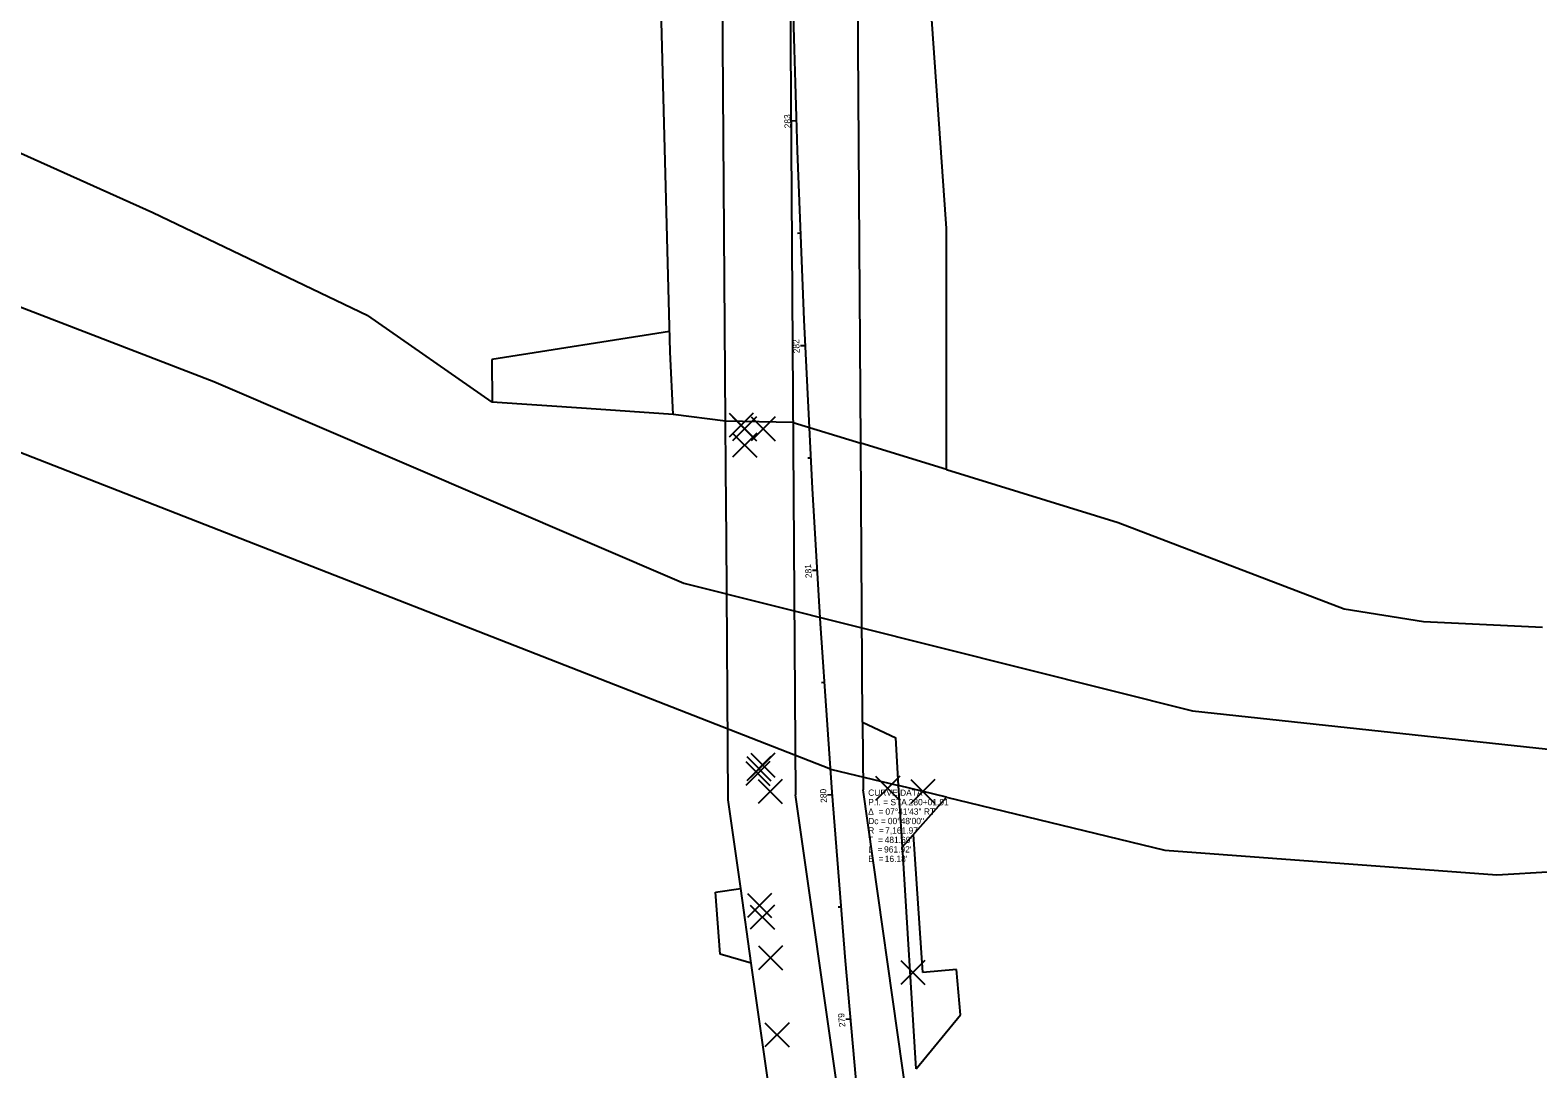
# Model space of a CAD drawing. Extents: x 1721910 to 1725197, y 328771 to 332519.
# Drawn here: x 1722580 to 1723250, y 330805 to 331267 of the extents above; entities that cross this region are included whole.
import ezdxf

# ---------------------------------------------------------------- set-up
doc = ezdxf.new("R2010")
doc.units = 0
for name, color, linetype in [('BR_P_Gen_Approach_Slab', 7, 'Continuous'), ('BR_P_Slab_Object', 7, 'Continuous'), ('DR_P_Ditch', 7, 'Continuous'), ('DR_P_Flood_Boundary', 7, 'Continuous'), ('DT_P_Graded_Shoulder', 7, 'Continuous'), ('MT_P_Work_Area', 7, 'Continuous'), ('PM_X_Lane_Line', 7, 'Continuous'), ('PV_P_Drive', 7, 'Continuous'), ('PV_P_EOP', 7, 'Continuous'), ('RD_P_GR_Rt', 7, 'Continuous'), ('SC_Scratch1', 7, 'Continuous')]:
    doc.layers.add(name, color=color, linetype=linetype)

msp = doc.modelspace()

# ---------------------------------------------------------------- linework, layer by layer
at = {"layer": 'BR_P_Gen_Approach_Slab'}
for p, q in [((1722889.04, 331093.19), (1722884.82, 331710.44)), ((1722949.11, 331083.44), (1722944.82, 331710.85)), ((1722916.88, 331408.8), (1722920.17, 330927.13)), ((1722949.95, 330959.48), (1722950.16, 330929.35)), ((1722978.45, 330730.26), (1722950.16, 330929.35)), ((1722987.94, 330450.23), (1722920.17, 330927.13))]:
    msp.add_line(p, q, dxfattribs=at)
at = {"layer": 'BR_P_Slab_Object'}
msp.add_lwpolyline([(1722131.62, 331191.29), (1722412.26, 331207.03), (1722661.62, 331110.8), (1722870.54, 331021.28), (1723096.57, 330964.56), (1723308.08, 330941.73), (1723482.96, 330982.54)], dxfattribs=at)
at = {"layer": 'DR_P_Flood_Boundary'}
for p, q in [((1722864.19, 331133.05), (1722785.15, 331120.7)), ((1722785.15, 331120.7), (1722785.4, 331101.7)), ((1722827.29, 331098.84), (1722785.4, 331101.7)), ((1722865.77, 331096.21), (1722827.29, 331098.84))]:
    msp.add_line(p, q, dxfattribs=at)
at = {"layer": 'DT_P_Graded_Shoulder'}
msp.add_arc((1730078.68, 331457.77), 7161.97, 180.391728, 188.087121, dxfattribs=at)
at = {"layer": 'MT_P_Work_Area'}
for p, q in [((1722890.66, 331096.78), (1722901.35, 331086.08)), ((1722901.35, 331096.78), (1722890.66, 331086.08)), ((1722892.17, 331095.14), (1722902.86, 331084.45)), ((1722902.86, 331095.14), (1722892.17, 331084.45)), ((1722896, 331091.43), (1722896, 331091.43)), ((1722897.51, 331089.8), (1722897.51, 331089.8)), ((1722900.38, 331095.15), (1722911.07, 331084.46)), ((1722911.07, 331095.15), (1722900.38, 331084.46)), ((1722905.72, 331089.81), (1722905.72, 331089.81)), ((1722892.19, 331087.95), (1722902.88, 331077.26)), ((1722902.88, 331087.95), (1722892.19, 331077.26)), ((1722897.53, 331082.6), (1722897.53, 331082.6)), ((1722898.01, 330942.01), (1722908.7, 330931.32)), ((1722908.7, 330942.01), (1722898.01, 330931.32)), ((1722898.48, 330944.13), (1722909.17, 330933.44)), ((1722909.17, 330944.13), (1722898.48, 330933.44)), ((1722900.3, 330945.63), (1722910.99, 330934.94)), ((1722910.99, 330945.63), (1722900.3, 330934.94)), ((1722903.36, 330936.67), (1722903.36, 330936.67)), ((1722903.82, 330938.79), (1722903.82, 330938.79)), ((1722905.64, 330940.28), (1722905.64, 330940.28)), ((1722955.72, 330935.39), (1722966.41, 330924.69)), ((1722966.41, 330935.39), (1722955.72, 330924.69)), ((1722903.54, 330933.95), (1722914.23, 330923.26)), ((1722914.23, 330933.95), (1722903.54, 330923.26)), ((1722908.88, 330928.61), (1722908.88, 330928.61)), ((1722961.06, 330930.04), (1722961.06, 330930.04)), ((1722971.37, 330934.04), (1722982.06, 330923.35)), ((1722982.06, 330934.04), (1722971.37, 330923.35)), ((1722976.72, 330928.69), (1722976.72, 330928.69)), ((1722898.82, 330883.31), (1722909.51, 330872.62)), ((1722909.51, 330883.31), (1722898.82, 330872.62)), ((1722900.03, 330878.16), (1722910.73, 330867.47)), ((1722910.73, 330878.16), (1722900.03, 330867.47)), ((1722904.17, 330877.96), (1722904.17, 330877.96)), ((1722905.38, 330872.82), (1722905.38, 330872.82)), ((1722903.61, 330860.05), (1722914.3, 330849.36)), ((1722914.3, 330860.05), (1722903.61, 330849.36)), ((1722908.96, 330854.71), (1722908.96, 330854.71)), ((1722966.95, 330853.59), (1722977.64, 330842.9)), ((1722977.64, 330853.59), (1722966.95, 330842.9)), ((1722972.29, 330848.24), (1722972.29, 330848.24)), ((1722906.54, 330825.79), (1722917.23, 330815.1)), ((1722917.23, 330825.79), (1722906.54, 330815.1)), ((1722911.89, 330820.45), (1722911.89, 330820.45))]:
    msp.add_line(p, q, dxfattribs=at)
at = {"layer": 'PM_X_Lane_Line'}
for p, q in [((1722785.4, 331101.7), (1722730.04, 331140.19)), ((1722935.69, 330938.62), (1722430.49, 331135.91)), ((1722827.29, 331098.84), (1722785.4, 331101.7)), ((1722865.77, 331096.21), (1722827.29, 331098.84)), ((1722889.04, 331093.19), (1722865.77, 331096.21)), ((1722919.04, 331092.69), (1722889.04, 331093.19)), ((1722919.04, 331092.69), (1722949.11, 331083.44)), ((1722987.21, 331071.69), (1722949.11, 331083.44)), ((1722987.21, 331071.71), (1723063.42, 331048.26)), ((1723063.42, 331048.26), (1723163.91, 331009.86)), ((1723163.91, 331009.86), (1723199.1, 331004.21)), ((1723199.1, 331004.21), (1723251.95, 331001.61)), ((1722935.69, 330938.62), (1722965.95, 330931.27)), ((1722987.24, 330926.09), (1722965.95, 330931.27)), ((1722987.24, 330926.09), (1723084.16, 330902.53)), ((1723084.16, 330902.53), (1723231.76, 330891.66)), ((1723231.76, 330891.66), (1723256.72, 330893.13))]:
    msp.add_line(p, q, dxfattribs=at)
msp.add_lwpolyline([(1722434.29, 331257.93), (1722539.23, 331228.82), (1722634.57, 331186.03), (1722730.04, 331140.19)], dxfattribs=at)
at = {"layer": 'PV_P_Drive'}
for p, q in [((1722976.7, 330848.17), (1722972.57, 330909.58)), ((1722884.54, 330883.91), (1722895.79, 330885.51)), ((1722886.71, 330856.33), (1722884.54, 330883.91)), ((1722900.49, 330852.39), (1722886.71, 330856.33)), ((1722991.69, 330849.48), (1722976.7, 330848.17)), ((1722993.45, 330829.33), (1722991.69, 330849.48)), ((1722973.78, 330805.37), (1722993.45, 330829.33))]:
    msp.add_line(p, q, dxfattribs=at)
at = {"layer": 'PV_P_EOP'}
for p, q in [((1722864.43, 331124), (1722856.88, 331408.39)), ((1722987.21, 331071.69), (1722987.2, 331178.83)), ((1722865.77, 331096.21), (1722864.43, 331124)), ((1722889.04, 331093.19), (1722865.77, 331096.21)), ((1722889.18, 331071.89), (1722889.04, 331093.19)), ((1722949.95, 330959.48), (1722949.11, 331083.44)), ((1722987.21, 331071.69), (1722949.11, 331083.44)), ((1722889.4, 331040.83), (1722889.18, 331071.89)), ((1722890.19, 330924.9), (1722889.4, 331040.83)), ((1722949.95, 330959.48), (1722964.63, 330952.5)), ((1722965.95, 330931.27), (1722964.63, 330952.5)), ((1722967.65, 330904.04), (1722965.95, 330931.27)), ((1722895.79, 330885.51), (1722890.19, 330924.9)), ((1722973.78, 330805.37), (1722967.65, 330904.04)), ((1722900.49, 330852.39), (1722895.79, 330885.51)), ((1722916.51, 330739.69), (1722900.49, 330852.39))]:
    msp.add_line(p, q, dxfattribs=at)
msp.add_lwpolyline([(1722987.2, 331178.83), (1722949.82, 331710.89), (1722944.82, 331710.85), (1722944.78, 331715.74)], dxfattribs=at)
at = {"layer": 'RD_P_GR_Rt'}
msp.add_line((1722967.65, 330904.04), (1722987.24, 330926.09), dxfattribs=at)
at = {"layer": 'SC_Scratch1'}
for p, q in [((1722920.44, 331226.69), (1722918.44, 331226.63)), ((1722922.23, 331176.73), (1722921.03, 331176.68)), ((1722924.37, 331126.77), (1722922.37, 331126.68)), ((1722926.85, 331076.83), (1722925.65, 331076.77)), ((1722929.69, 331026.91), (1722927.69, 331026.79)), ((1722932.87, 330977.02), (1722931.67, 330976.94)), ((1722936.4, 330927.14), (1722934.4, 330926.99)), ((1722940.28, 330877.29), (1722939.08, 330877.19)), ((1722944.5, 330827.47), (1722942.51, 330827.29))]:
    msp.add_line(p, q, dxfattribs=at)

# ---------------------------------------------------------------- texts
at = {"layer": 'DR_P_Ditch'}
for s, p in [('CURVE DATA', (1722952.41, 330926.72)), ('P.I. = STA. ', (1722952.41, 330922.52)), ('280+01.91', (1722970.4, 330922.52)), ('Δ  = ', (1722952.41, 330918.32)), ('Dc = ', (1722952.41, 330914.12)), ('07°41\'43" RT', (1722960.06, 330918.32)), ('00°48\'00"', (1722961.15, 330914.12)), ('T  = ', (1722952.41, 330905.72)), ('R  = ', (1722952.41, 330909.92)), ("481.69'", (1722959.73, 330905.72)), ("7,161.97'", (1722959.94, 330909.92)), ('L  = ', (1722952.41, 330901.52)), ("961.92'", (1722959.45, 330901.52)), ('E  = ', (1722952.41, 330897.32)), ("16.18'", (1722959.75, 330897.32))]:
    msp.add_text(s, height=2.8, dxfattribs=at).set_placement(p)
at = {"layer": 'SC_Scratch1'}
for s, rotation, p in [('283', 91.84891, (1722918.05, 331223.42)), ('282', 92.64891, (1722922.02, 331123.45)), ('281', 93.44891, (1722927.38, 331023.55)), ('280', 94.24891, (1722934.15, 330923.7)), ('279', 95.04891, (1722942.3, 330824.04))]:
    msp.add_text(s, height=2.8, rotation=rotation, dxfattribs=at).set_placement(p)

doc.saveas('drawing.dxf')
